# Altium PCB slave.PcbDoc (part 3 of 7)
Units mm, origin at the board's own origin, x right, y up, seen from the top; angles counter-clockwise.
Board outline 160 x 100 mm, 6 copper layers (Top, FUSED_VBAT-, Signals1, Signals2, SUPPLY, Bottom), stack 1.67 mm thick; 597 components, 381 nets, 1695 pads, 3028 vias.
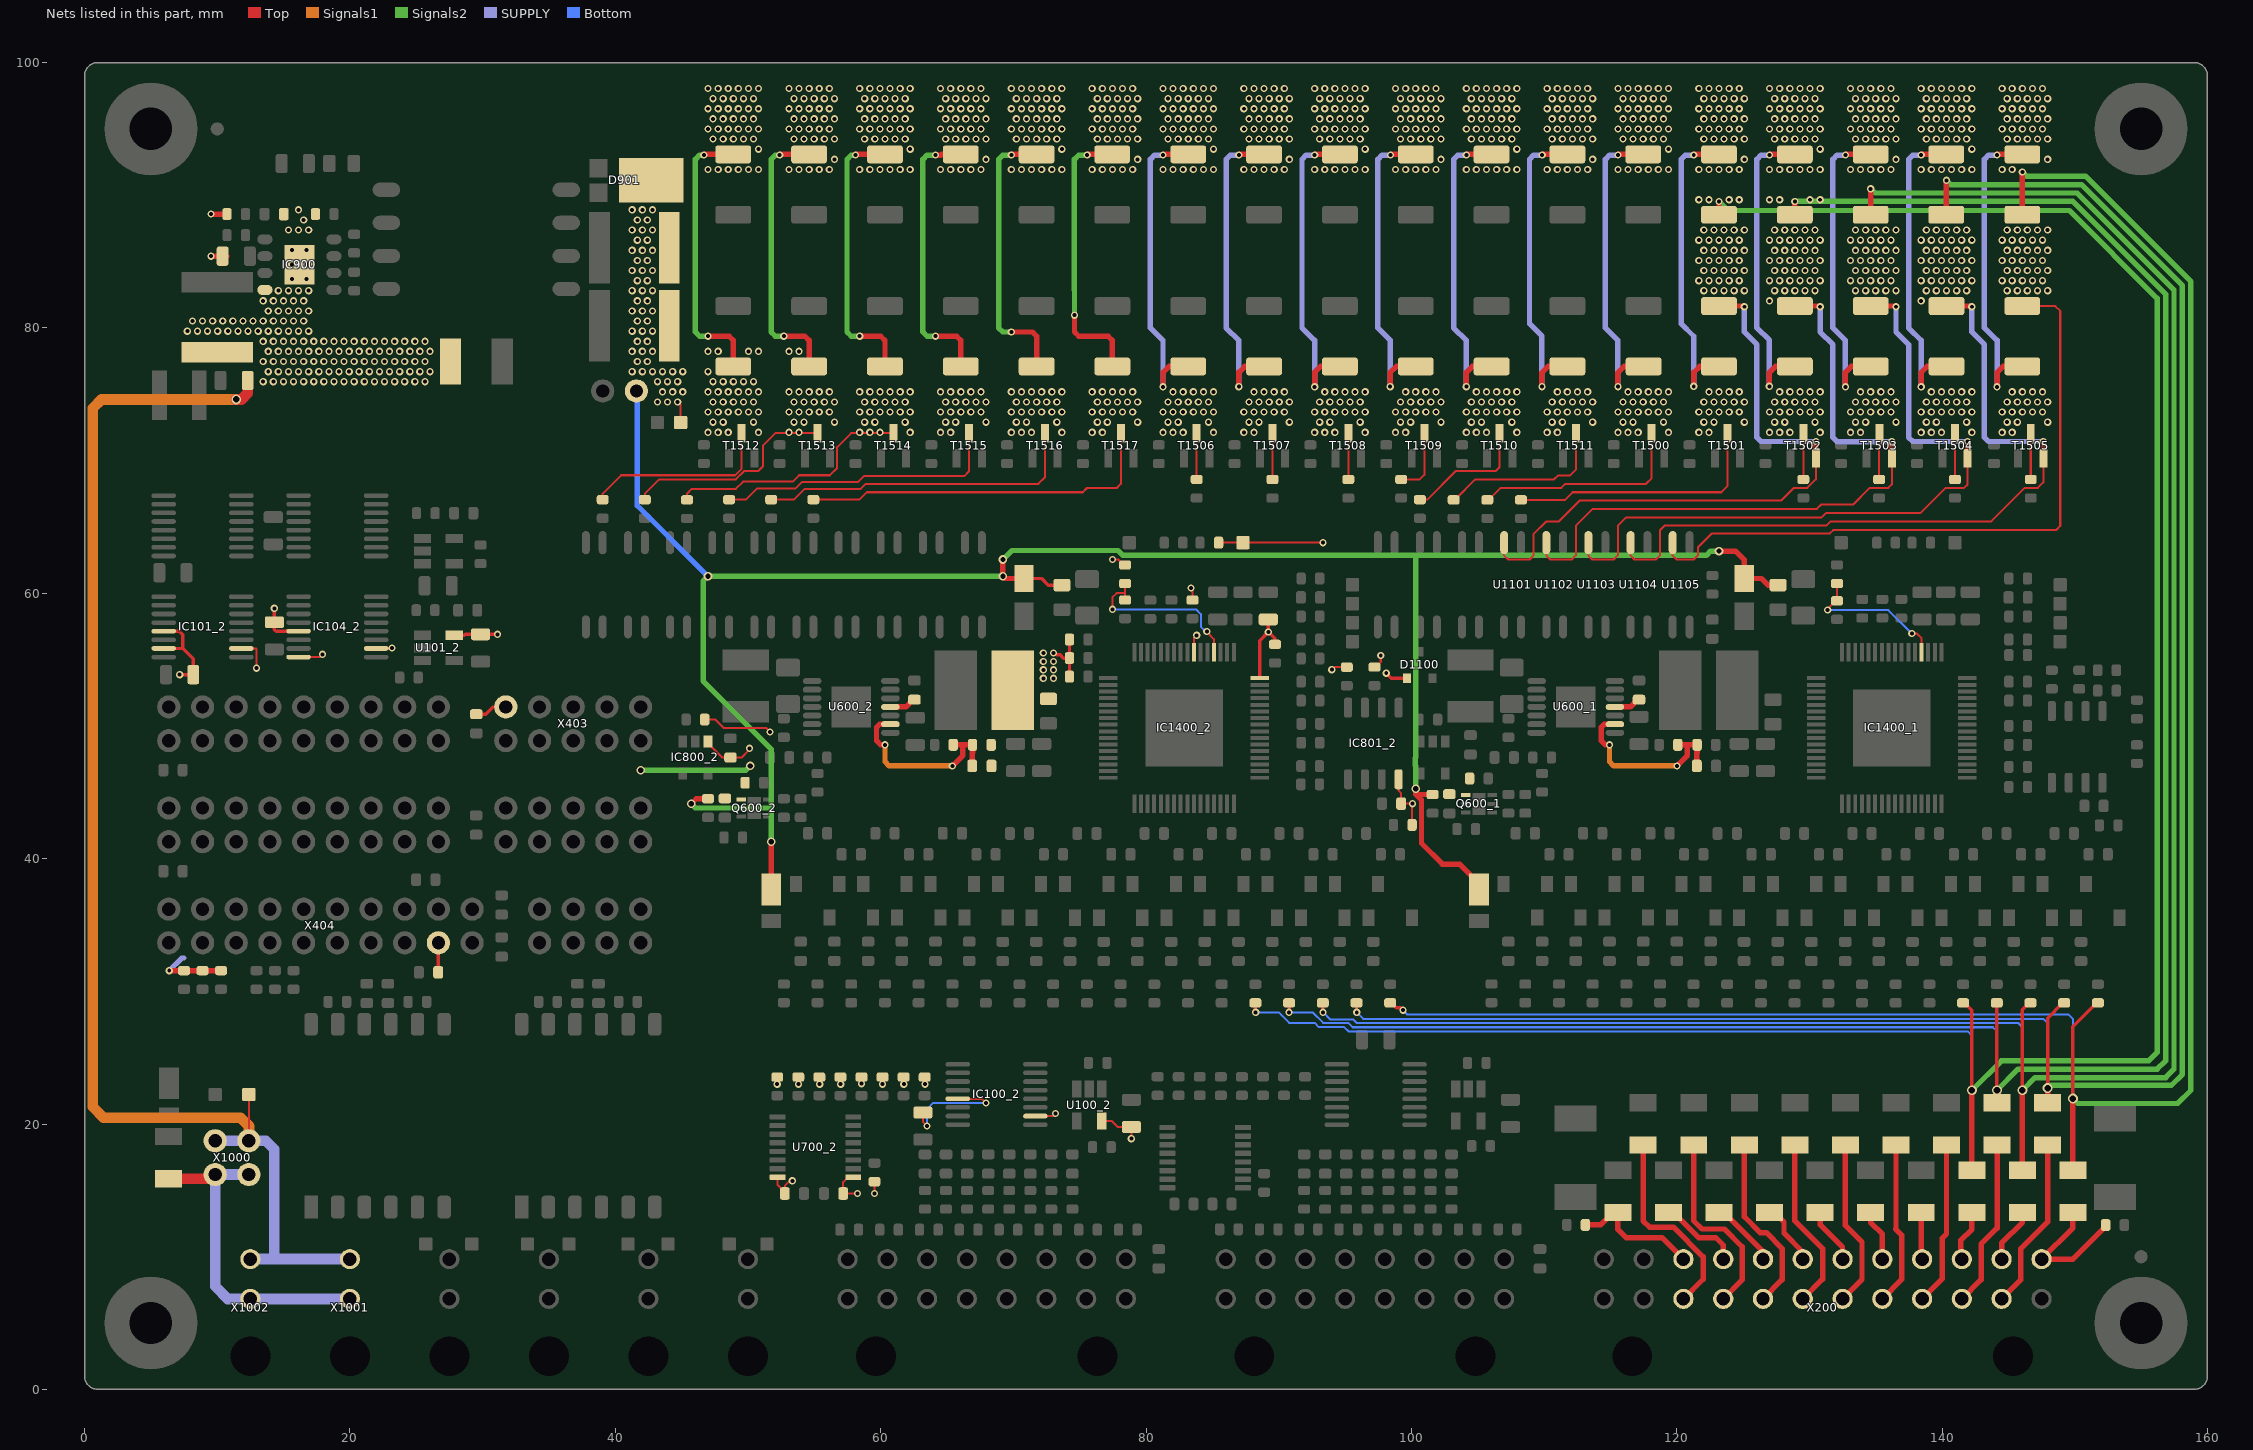
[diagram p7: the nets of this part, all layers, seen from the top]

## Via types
v1: diameter 0.55, hole 0.3, Top to Bottom, tented both sides, 2990 vias
v2: diameter 0.75, hole 0.5, Top to Bottom, tented both sides, 22 vias
v3: diameter 0.65, hole 0.4, Top to Bottom, tented both sides, 16 vias

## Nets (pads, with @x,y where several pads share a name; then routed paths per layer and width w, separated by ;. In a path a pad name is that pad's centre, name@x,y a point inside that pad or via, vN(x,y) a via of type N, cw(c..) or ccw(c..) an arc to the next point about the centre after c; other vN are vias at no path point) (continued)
+5.0V_VREG_1: C101_2.2 C102_2.2 C103_2.2 C104_2.2 C105_2.2 C403.2 C407.2 C604_2.2 C700_2.2 C701_2.2 C800_2.2 C801_2.2 C1401_2.2 D1100.1 IC100_2.2 IC100_2.13 IC101_2.2 IC101_2.13 IC101_2.15 IC104_2.2 IC104_2.13 IC104_2.16 IC800_2.1 IC801_2.8 IC1400_2.48 IC1400_2.55 L600_2.2 LD1400_2.2 R602_2.1 R604_2.1 R700_2.2 R701_2.2 R702_2.2 R703_2.2 R704_2.2 R705_2.2 R706_2.2 R707_2.2 R708_2.1 R800_2.2 R801_2.2 R1404_2.2 R1407_2.2 R1419_2.2 R1420_2.2 R1421_2.2 R1422_2.2 R1423_2.2 R1424_2.2 R1425_2.2 R1426_2.2 R1427_2.2 TP1403_2.1 U100_2.5 U101_2.5 U700_2.1 U700_2.16 X403.9 X404.4 | length 102.8
  Top w0.152: IC101_2.2@11.786,55.842 12.921,55.842 12.954,55.809 v1(12.954,54.356) ; IC104_2.16@16.125,55.193 17.728,55.193 v1(17.939,55.404) ; IC104_2.2@21.946,55.842 23.139,55.842 v1(23.177,55.88) ; R800_2.2@46.737,50.482 47.554,50.482 48.189,49.847 51.363,49.847 v1(51.663,49.548) ; IC800_2.1@46.988,48.825 46.988,48.7 48.063,47.625 C800_2.2@48.677,47.625 49.53,47.625 50.109,48.204 v1(50.109,48.316) ; v1(52.205,23.006) R707_2.2@52.205,23.535 R707_2.2@52.205,23.585 ; U700_2.16@52.236,15.981 52.236,15.401 C700_2.2@52.774,14.864 ; C700_2.2@52.774,14.764 C700_2.2@52.774,14.864 ; v1(53.34,15.716) 53.15,15.716 52.774,15.34 C700_2.2@52.774,14.864 ; R706_2.2@53.792,23.535 53.792,23.026 v1(53.813,23.006) ; R706_2.2@53.792,23.585 53.813,23.565 R706_2.2@53.813,23.535 ; R705_2.2@55.38,23.535 55.38,23.026 v1(55.4,23.006) ; R705_2.2@55.38,23.585 55.4,23.565 R705_2.2@55.4,23.535 ; R704_2.2@56.967,23.535 56.967,23.026 v1(56.988,23.006) ; R704_2.2@56.967,23.585 56.988,23.565 R704_2.2@56.988,23.535 ; U700_2.1@57.936,15.981 57.536,15.981 57.18,15.625 C701_2.2@57.18,14.764 v1(58.261,14.764) ; v1(58.555,23.044) R703_2.2@58.555,23.535 ; R703_2.2@58.555,23.585 R703_2.2@58.58,23.56 ; v1(59.531,14.764) R708_2.1@59.531,15.651 ; v1(60.142,23.006) R702_2.2@60.142,23.535 R702_2.2@60.142,23.585 ; R701_2.2@61.73,23.535 61.73,23.026 v1(61.75,23.006) ; R701_2.2@61.73,23.585 61.75,23.565 R701_2.2@61.75,23.535 ; C101_2.2@63.182,20.869 63.182,20.161 v1(63.5,19.844) ; R700_2.2@63.317,23.535 63.317,23.026 v1(63.338,23.006) ; R700_2.2@63.317,23.585 63.338,23.565 R700_2.2@63.338,23.535 ; IC100_2.13@65.814,21.9 67.635,21.9 v1(67.945,21.59) ; IC100_2.2@71.664,20.6 72.988,20.6 v1(73.184,20.796) 73.184,20.637 v1@73.146,20.6 ; U100_2.5@76.674,20.231 77.4,20.231 77.86,19.771 C103_2.2@78.899,19.771 v1(78.899,18.891) ; v1(77.47,62.547) 77.911,62.547 78.323,62.136 R1407_2.2@78.422,62.136 ; v1(83.384,60.397) 83.502,60.279 R1404_2.2@83.502,59.488 ; IC1400_2.55@83.618,55.598 83.618,56.63 v1(83.82,56.832) ; LD1400_2.2@85.523,63.817 TP1403_2.1@87.312,63.817 v1(93.345,63.817) ; v1(94.005,54.245) 94.194,54.434 R1419_2.2@95.135,54.434 ; R1420_2.2@97.223,54.437 97.323,54.437 97.693,54.808 v1(97.693,55.309) ; IC801_2.8@99.04,45.98 99.04,45.128 99.235,44.933 C801_2.2@99.235,44.147 v1(100.081,44.147) 100.057,44.124 R801_2.2@100.057,42.545
  Top w0.254: IC101_2.15@5.965,55.843 7.403,55.843 ; IC101_2.13@5.965,57.143 7.119,57.143 7.396,56.866 7.396,55.85 7.403,55.843 ; v1(7.166,53.868) C102_2.2@8.191,53.868 8.191,55.055 7.403,55.843 ; v1(14.306,58.864) C105_2.2@14.306,57.818 14.306,57.266 14.429,57.143 IC104_2.13@16.125,57.143 ; C407.2@26.65,31.432 C407.2@26.65,31.5 ; C407.2@26.67,31.52 C407.2@26.65,31.5 ; X404.4@26.67,33.655 26.65,33.635 C407.2@26.65,31.507 ; U101_2.5@27.87,56.83 28.622,56.83 28.697,56.905 C104_2.2@29.845,56.905 v1(31.115,56.905) ; C403.2@29.527,50.89 30.245,50.89 30.777,51.423 X403.9@31.75,51.435 ; 73.279,55.372 73.524,55.372 73.778,55.118 R1422_2.2@74.23,55.118 ; R1421_2.2@74.23,53.721 R1422_2.2@74.23,55.118 ; R1423_2.2@74.23,56.515 R1422_2.2@74.23,55.118 ; IC1400_2.48@88.568,53.597 88.568,56.433 v1(89.218,57.083) ; C1401_2.2@89.218,58.03 v1(89.218,57.083) ; R1424_2.2@89.725,56.152 89.725,56.604 89.697,56.604 v1(89.218,57.083) ; v1(98.108,53.975) 98.485,53.598 D1100.1@99.677,53.598 ; C407.2@26.65,31.5 26.583,31.432 26.613,31.466 C407.2@26.65,31.507 ; C407.2@26.65,31.5 C407.2@26.65,31.507
  Top w0.406: v1@6.35,31.561 v1(6.381,31.561) R1427_2.2@7.493,31.561 R1426_2.2@8.89,31.561 R1425_2.2@10.287,31.561
  Signals2 w0.406: v3(41.91,46.672) 49.847,46.672 v3(50.165,46.99)
  SUPPLY w0.406: v1(6.381,31.561) 7.332,32.512 7.493,32.512
  Bottom w0.152: v1(63.5,19.844) 63.5,21.114 63.976,21.59 v1(67.945,21.59)
  other v1: 72.263,53.594 73.025,53.594 72.263,54.229 73.025,54.229 72.263,54.864 73.025,54.864 72.263,55.499 73.025,55.499
BST_1: C602_1.2 U600_1.11 | length 2
  Top w0.406: U600_1.11@115.345,51.435 116.513,51.435 117.058,51.98 C602_1.2@117.157,51.98
BST_2: C602_2.2 U600_2.11 | length 2
  Top w0.406: U600_2.11@60.735,51.435 61.903,51.435 62.448,51.98 C602_2.2@62.547,51.98
CELL_0+: F318.1 X200.2 | length 13.3
  Top w0.406: X200.2@144.487,6.818 145.94,8.271 145.94,10.611 147.955,12.626 F318.1@147.955,18.413 ; F318.1@147.955,18.413 F318.1@147.955,18.652
CELL_0-: F319.1 SJ301.1 X200.13 | length 10.5
  Top w0.406: F319.1@149.86,13.333 149.86,12.178 X200.13@147.497,9.815 149.868,9.815 152.335,12.283 SJ301.1@152.335,12.383
CELL_1+: F317.1 X200.14 | length 4.2
  Top w0.406: X200.14@144.487,9.815 144.487,11.018 146.05,12.581 F317.1@146.05,13.333
CELL_2+: F316.1 X200.3 | length 12.9
  Top w0.406: X200.3@141.49,6.818 142.945,8.273 142.945,10.954 144.145,12.154 F316.1@144.145,18.413 ; F316.1@144.145,18.413 F316.1@144.145,18.652
CELL_3+: F315.1 X200.15 | length 3.9
  Top w0.406: X200.15@141.49,9.815 141.415,9.89 141.415,11.24 142.24,12.065 F315.1@142.24,13.333
CELL_4+: F314.1 X200.4 | length 12.6
  Top w0.406: X200.4@138.493,6.818 140.017,8.343 140.017,11.407 140.335,11.725 F314.1@140.335,18.413 ; F314.1@140.335,18.413 F314.1@140.335,18.652
CELL_5+: F313.1 X200.16 | length 3.5
  Top w0.406: F313.1@138.43,13.333 138.43,9.878 X200.16@138.493,9.815
CELL_6+: F312.1 X200.5 | length 12.6
  Top w0.406: X200.5@135.496,6.818 136.955,8.277 136.955,11.635 136.505,12.085 136.525,12.105 F312.1@136.525,18.413 ; F312.1@136.525,18.413 F312.1@136.525,18.652
CELL_7+: F311.1 X200.17 | length 3.9
  Top w0.406: F311.1@134.62,13.333 134.62,12.581 135.496,11.705 X200.17@135.496,9.815
CELL_8+: F310.1 X200.6 | length 13
  Top w0.406: X200.6@132.499,6.818 133.965,8.284 133.965,11.105 132.715,12.355 F310.1@132.715,18.413 F310.1@132.715,18.652
CELL_9+: F309.1 X200.18 | length 4.2
  Top w0.406: F309.1@130.81,13.333 130.81,12.415 132.499,10.726 X200.18@132.499,9.815
CELL_10+: F308.1 X200.7 | length 13.3
  Top w0.406: F308.1@128.905,18.652 F308.1@128.905,18.413 128.905,12.7 130.994,10.611 130.994,8.311 X200.7@129.501,6.818
CELL_11+: F307.1 X200.19 | length 4.8
  Top w0.406: F307.1@127,13.333 127.365,13.333 128.087,12.611 128.087,11.772 129.501,10.358 X200.19@129.501,9.815
CELL_12+: F306.1 X200.8 | length 13.9
  Top w0.406: F306.1@125.095,18.652 F306.1@125.095,18.413 125.095,13.01 126.288,11.817 126.754,11.817 127.953,10.619 127.953,8.267 X200.8@126.504,6.818
CELL_13+: F305.1 X200.20 | length 5.1
  Top w0.406: F305.1@123.19,13.333 123.555,13.333 126.504,10.384 X200.20@126.504,9.815
CELL_14+: F304.1 X200.9 | length 14.9
  Top w0.406: F304.1@121.285,18.652 F304.1@121.285,18.413 121.285,12.704 121.904,12.085 123.6,12.085 124.936,10.749 124.936,8.247 X200.9@123.507,6.818
CELL_15+: F303.1 X200.21 | length 6.2
  Top w0.406: F303.1@119.38,13.333 119.745,13.333 121.648,11.43 122.943,11.43 123.507,10.866 X200.21@123.507,9.815
CELL_16+: F302.1 X200.10 | length 15.4
  Top w0.406: F302.1@117.475,18.652 F302.1@117.475,18.413 117.475,12.7 117.951,12.224 119.754,12.224 121.99,9.987 121.99,8.298 X200.10@120.51,6.818
CELL_17+: F301.1 SJ300.2 X200.22 | length 10
  Top w0.406: SJ300.2@113.115,12.395 114.267,12.395 115.205,13.333 F301.1@115.57,13.333 115.57,12.047 116.187,11.43 118.895,11.43 X200.22@120.51,9.815
CELL_FEEDBACK.CELL0_FEEDBACK+: R1105.1 R1505.2 R1511.2 T1505.3 | length 27.2
  Top w0.152: R1105.1@146.685,68.58 T1505.3@146.685,72.07
  Top w0.406: v1(144.145,75.565) 144.145,76.647 144.598,77.1 R1505.2@146.05,77.1 ; v1(144.145,93.027) 144.198,93.08 R1511.2@146.05,93.08
  SUPPLY w0.406: v1(144.145,75.565) 144.145,79.057 143.192,80.01 143.192,92.71 143.51,93.027 v1(144.145,93.027)
  other v1: 144.526,72.136 145.288,72.136 144.907,72.898 145.669,72.898 147.955,72.898 144.526,73.66 145.288,73.66 146.05,73.66 146.812,73.66 147.574,73.66 144.907,74.422 145.669,74.422 146.431,74.422 147.193,74.422 147.955,74.422 145.288,75.184 146.05,75.184 146.812,75.184 147.574,75.184 144.526,91.948 145.288,91.948 147.955,92.71 144.907,94.234 145.669,94.234 146.431,94.234 147.193,94.234 147.955,94.234 144.526,94.996 145.288,94.996 146.05,94.996 146.812,94.996 147.574,94.996 144.907,95.758 145.669,95.758 146.431,95.758 147.193,95.758 147.955,95.758 144.526,96.52 145.288,96.52 146.05,96.52 146.812,96.52 147.574,96.52 144.907,97.282 145.669,97.282 146.431,97.282 147.193,97.282 147.955,97.282 144.526,98.044 145.288,98.044 146.05,98.044 146.812,98.044 147.574,98.044
CELL_FEEDBACK.CELL1_FEEDBACK+: R1104.1 R1504.2 R1510.2 T1504.3 | length 27.2
  Top w0.152: R1104.1@140.97,68.58 T1504.3@140.97,72.07
  Top w0.406: v1(138.43,75.565) 138.43,76.647 138.883,77.1 R1504.2@140.335,77.1 ; v1(138.43,93.027) 138.483,93.08 R1510.2@140.315,93.08
  SUPPLY w0.406: v1(138.43,75.565) 138.43,79.057 137.477,80.01 137.477,92.71 137.795,93.027 v1(138.43,93.027)
  other v1: 138.43,72.136 139.192,72.136 139.954,72.136 142.24,72.136 138.811,72.898 139.573,72.898 141.859,72.898 138.43,73.66 139.192,73.66 139.954,73.66 140.716,73.66 141.478,73.66 142.24,73.66 138.811,74.422 139.573,74.422 140.335,74.422 141.097,74.422 141.859,74.422 139.192,75.184 139.954,75.184 140.716,75.184 141.478,75.184 142.24,75.184 138.43,91.948 139.192,91.948 139.954,91.948 140.716,91.948 141.478,91.948 142.24,91.948 142.24,93.472 138.811,94.234 139.573,94.234 140.335,94.234 141.097,94.234 141.859,94.234 138.43,94.996 139.192,94.996 139.954,94.996 140.716,94.996 141.478,94.996 142.24,94.996 138.811,95.758 139.573,95.758 140.335,95.758 141.097,95.758 141.859,95.758 138.43,96.52 139.192,96.52 139.954,96.52 140.716,96.52 141.478,96.52 142.24,96.52 138.811,97.282 139.573,97.282 140.335,97.282 141.097,97.282 141.859,97.282 138.43,98.044 139.192,98.044 139.954,98.044 140.716,98.044 141.478,98.044 142.24,98.044
CELL_FEEDBACK.CELL2_FEEDBACK+: R1103.1 R1503.2 R1509.2 T1503.3 | length 27.2
  Top w0.152: R1103.1@135.255,68.58 135.255,71.256 135.267,71.268 T1503.3@135.267,72.07
  Top w0.406: v1(132.715,75.565) 132.715,76.647 133.168,77.1 R1503.2@134.62,77.1 ; v1(132.715,93.027) 132.768,93.08 R1509.2@134.62,93.08
  SUPPLY w0.406: v1(132.715,75.565) 132.715,79.057 131.762,80.01 131.762,92.71 132.08,93.027 v1(132.715,93.027)
  other v1: 133.096,72.136 133.858,72.136 133.477,72.898 134.239,72.898 136.525,72.898 133.096,73.66 133.858,73.66 134.62,73.66 135.382,73.66 136.144,73.66 133.477,74.422 134.239,74.422 135.001,74.422 135.763,74.422 136.525,74.422 133.858,75.184 134.62,75.184 135.382,75.184 136.144,75.184 133.096,91.948 133.858,91.948 134.62,91.948 135.382,91.948 136.144,91.948 136.525,92.71 133.477,94.234 134.239,94.234 135.001,94.234 135.763,94.234 136.525,94.234 133.096,94.996 133.858,94.996 134.62,94.996 135.382,94.996 136.144,94.996 133.477,95.758 134.239,95.758 135.001,95.758 135.763,95.758 136.525,95.758 133.096,96.52 133.858,96.52 134.62,96.52 135.382,96.52 136.144,96.52 133.477,97.282 134.239,97.282 135.001,97.282 135.763,97.282 136.525,97.282 133.096,98.044 133.858,98.044 134.62,98.044 135.382,98.044 136.144,98.044
CELL_FEEDBACK.CELL3_FEEDBACK+: R1102.1 R1502.2 R1508.2 T1502.3 | length 27.2
  Top w0.152: R1102.1@129.54,68.58 T1502.3@129.54,72.07
  Top w0.406: v1(126.982,75.595) 126.982,76.628 127.453,77.1 R1502.2@128.905,77.1 ; v1(127,93.027) 127.053,93.08 R1508.2@128.905,93.08
  SUPPLY w0.406: v1@127,75.614 v1(126.982,75.595) 126.982,79.076 126.047,80.01 126.047,92.71 126.365,93.027 v1(127,93.027)
  other v1: 127,72.136 127.762,72.136 128.524,72.136 130.81,72.136 127.381,72.898 128.143,72.898 130.429,72.898 127,73.66 127.762,73.66 128.524,73.66 129.286,73.66 130.048,73.66 130.81,73.66 127.381,74.422 128.143,74.422 128.905,74.422 129.667,74.422 130.429,74.422 127.762,75.184 128.524,75.184 129.286,75.184 130.048,75.184 130.81,75.184 127,91.948 127.762,91.948 128.524,91.948 129.286,91.948 130.048,91.948 130.81,91.948 130.81,93.472 127.381,94.234 128.143,94.234 128.905,94.234 129.667,94.234 130.429,94.234 127,94.996 127.762,94.996 128.524,94.996 129.286,94.996 130.048,94.996 130.81,94.996 127.381,95.758 128.143,95.758 128.905,95.758 129.667,95.758 130.429,95.758 127,96.52 127.762,96.52 128.524,96.52 129.286,96.52 130.048,96.52 130.81,96.52 127.381,97.282 128.143,97.282 128.905,97.282 129.667,97.282 130.429,97.282 127,98.044 127.762,98.044 128.524,98.044 129.286,98.044 130.048,98.044 130.81,98.044
CELL_FEEDBACK.CELL4_FEEDBACK+: R1101.1 R1501.2 R1507.2 T1501.3 | length 43.6
  Top w0.152: R1101.1@108.267,67.045 111.587,67.045 112.157,67.615 123.36,67.615 123.825,68.08 T1501.3@123.825,72.07
  Top w0.406: v1(121.285,75.595) 121.285,76.647 121.738,77.1 R1501.2@123.19,77.1 ; v1(121.285,93.027) 121.338,93.08 R1507.2@123.19,93.08
  SUPPLY w0.406: v1(121.285,75.595) 121.285,79.375 120.332,80.328 120.332,92.71 120.65,93.027 v1(121.285,93.027)
  other v1: 121.666,72.136 122.428,72.136 122.047,72.898 122.809,72.898 125.095,72.898 121.666,73.66 122.428,73.66 123.19,73.66 123.952,73.66 124.714,73.66 122.047,74.422 122.809,74.422 123.571,74.422 124.333,74.422 125.095,74.422 122.428,75.184 123.19,75.184 123.952,75.184 124.714,75.184 121.666,91.948 122.428,91.948 123.19,91.948 123.952,91.948 124.714,91.948 125.095,92.71 122.047,94.234 122.809,94.234 123.571,94.234 124.333,94.234 125.095,94.234 121.666,94.996 122.428,94.996 123.19,94.996 123.952,94.996 124.714,94.996 122.047,95.758 122.809,95.758 123.571,95.758 124.333,95.758 125.095,95.758 121.666,96.52 122.428,96.52 123.19,96.52 123.952,96.52 124.714,96.52 122.047,97.282 122.809,97.282 123.571,97.282 124.333,97.282 125.095,97.282 121.666,98.044 122.428,98.044 123.19,98.044 123.952,98.044 124.714,98.044
CELL_FEEDBACK.CELL5_FEEDBACK+: R1100.1 R1500.2 R1506.2 T1500.3 | length 40.2
  Top w0.152: R1100.1@105.727,67.045 105.827,67.045 106.727,67.945 111.308,67.945 111.613,68.25 117.688,68.25 118.11,68.673 T1500.3@118.11,72.07
  Top w0.406: v1(115.57,75.575) 115.57,76.627 116.043,77.1 R1500.2@117.505,77.1 ; v1(115.57,93.027) 115.623,93.08 R1506.2@117.475,93.08
  SUPPLY w0.406: v1(115.57,75.575) 115.57,79.057 114.617,80.01 114.617,92.71 114.935,93.027 v1(115.57,93.027)
  other v1: 115.57,72.136 116.332,72.136 117.094,72.136 119.38,72.136 115.951,72.898 116.713,72.898 118.999,72.898 115.57,73.66 116.332,73.66 117.094,73.66 117.856,73.66 118.618,73.66 119.38,73.66 115.951,74.422 116.713,74.422 117.475,74.422 118.237,74.422 118.999,74.422 116.332,75.184 117.094,75.184 117.856,75.184 118.618,75.184 119.38,75.184 115.57,91.948 116.332,91.948 117.094,91.948 117.856,91.948 118.618,91.948 119.38,91.948 119.38,93.472 115.951,94.234 116.713,94.234 117.475,94.234 118.237,94.234 118.999,94.234 115.57,94.996 116.332,94.996 117.094,94.996 117.856,94.996 118.618,94.996 119.38,94.996 115.951,95.758 116.713,95.758 117.475,95.758 118.237,95.758 118.999,95.758 115.57,96.52 116.332,96.52 117.094,96.52 117.856,96.52 118.618,96.52 119.38,96.52 115.951,97.282 116.713,97.282 117.475,97.282 118.237,97.282 118.999,97.282 115.57,98.044 116.332,98.044 117.094,98.044 117.856,98.044 118.618,98.044 119.38,98.044
CELL_FEEDBACK.CELL6_FEEDBACK+: R1111.1 R1523.2 R1529.2 T1511.3 | length 36.6
  Top w0.152: R1111.1@103.188,67.045 103.287,67.045 104.824,68.581 110.754,68.581 111.057,68.885 111.965,68.885 112.395,69.315 T1511.3@112.395,72.07
  Top w0.406: v1(109.843,75.575) 109.843,76.634 110.308,77.1 R1523.2@111.76,77.1 ; v1(109.855,93.027) 109.908,93.08 R1529.2@111.76,93.08
  SUPPLY w0.406: v1@109.855,75.588 v1(109.843,75.575) 109.843,79.387 108.902,80.328 108.902,92.71 109.22,93.027 v1(109.855,93.027)
  other v1: 110.236,72.136 110.998,72.136 110.617,72.898 111.379,72.898 113.665,72.898 110.236,73.66 110.998,73.66 111.76,73.66 112.522,73.66 113.284,73.66 110.617,74.422 111.379,74.422 112.141,74.422 112.903,74.422 113.665,74.422 110.998,75.184 111.76,75.184 112.522,75.184 113.284,75.184 110.236,91.948 110.998,91.948 111.76,91.948 112.522,91.948 113.284,91.948 113.665,92.71 110.617,94.234 111.379,94.234 112.141,94.234 112.903,94.234 113.665,94.234 110.236,94.996 110.998,94.996 111.76,94.996 112.522,94.996 113.284,94.996 110.617,95.758 111.379,95.758 112.141,95.758 112.903,95.758 113.665,95.758 110.236,96.52 110.998,96.52 111.76,96.52 112.522,96.52 113.284,96.52 110.617,97.282 111.379,97.282 112.141,97.282 112.903,97.282 113.665,97.282 110.236,98.044 110.998,98.044 111.76,98.044 112.522,98.044 113.284,98.044
CELL_FEEDBACK.CELL7_FEEDBACK+: R1110.1 R1522.2 R1528.2 T1510.3 | length 33.3
  Top w0.152: R1110.1@100.642,67.058 101.194,67.058 103.356,69.22 106.362,69.22 106.66,69.517 T1510.3@106.66,72.07
  Top w0.406: v1(104.14,75.575) 104.14,76.647 104.593,77.1 R1522.2@106.045,77.1 ; v1(104.14,93.027) 104.193,93.08 R1528.2@106.045,93.08
  SUPPLY w0.406: v1(104.14,75.575) 104.14,79.057 103.188,80.01 103.188,92.71 103.505,93.027 v1(104.14,93.027)
  other v1: 104.14,72.136 104.902,72.136 105.664,72.136 107.95,72.136 104.521,72.898 105.283,72.898 107.569,72.898 104.14,73.66 104.902,73.66 105.664,73.66 106.426,73.66 107.188,73.66 107.95,73.66 104.521,74.422 105.283,74.422 106.045,74.422 106.807,74.422 107.569,74.422 104.902,75.184 105.664,75.184 106.426,75.184 107.188,75.184 107.95,75.184 104.14,91.948 104.902,91.948 105.664,91.948 106.426,91.948 107.188,91.948 107.95,91.948 107.95,93.472 104.521,94.234 105.283,94.234 106.045,94.234 106.807,94.234 107.569,94.234 104.14,94.996 104.902,94.996 105.664,94.996 106.426,94.996 107.188,94.996 107.95,94.996 104.521,95.758 105.283,95.758 106.045,95.758 106.807,95.758 107.569,95.758 104.14,96.52 104.902,96.52 105.664,96.52 106.426,96.52 107.188,96.52 107.95,96.52 104.521,97.282 105.283,97.282 106.045,97.282 106.807,97.282 107.569,97.282 104.14,98.044 104.902,98.044 105.664,98.044 106.426,98.044 107.188,98.044 107.95,98.044
CELL_FEEDBACK.CELL8_FEEDBACK+: R1109.1 R1521.2 R1527.2 T1509.3 | length 28.7
  Top w0.152: R1109.1@99.235,68.58 100.631,68.58 100.98,68.929 T1509.3@100.98,72.07
  Top w0.406: v1(98.405,75.575) 98.405,76.627 98.878,77.1 R1521.2@100.33,77.1 ; v1(98.425,93.027) 98.478,93.08 R1527.2@100.33,93.08
  SUPPLY w0.406: v1(98.405,75.575) 98.405,79.078 97.472,80.01 97.472,92.71 97.79,93.027 v1(98.425,93.027)
  other v1: 98.806,72.136 99.568,72.136 99.187,72.898 99.949,72.898 102.235,72.898 98.806,73.66 99.568,73.66 100.33,73.66 101.092,73.66 101.854,73.66 99.187,74.422 99.949,74.422 100.711,74.422 101.473,74.422 102.235,74.422 99.568,75.184 100.33,75.184 101.092,75.184 101.854,75.184 98.806,91.948 99.568,91.948 100.33,91.948 101.092,91.948 101.854,91.948 102.235,92.71 99.187,94.234 99.949,94.234 100.711,94.234 101.473,94.234 102.235,94.234 98.806,94.996 99.568,94.996 100.33,94.996 101.092,94.996 101.854,94.996 99.187,95.758 99.949,95.758 100.711,95.758 101.473,95.758 102.235,95.758 98.806,96.52 99.568,96.52 100.33,96.52 101.092,96.52 101.854,96.52 99.187,97.282 99.949,97.282 100.711,97.282 101.473,97.282 102.235,97.282 98.806,98.044 99.568,98.044 100.33,98.044 101.092,98.044 101.854,98.044
CELL_FEEDBACK.CELL9_FEEDBACK+: R1108.1 R1520.2 R1526.2 T1508.3 | length 27.2
  Top w0.152: R1108.1@95.25,68.58 T1508.3@95.25,72.07
  Top w0.406: v1(92.71,75.565) 92.71,76.647 93.163,77.1 R1520.2@94.615,77.1 ; v1(92.71,93.027) 92.763,93.08 R1526.2@94.615,93.08
  SUPPLY w0.406: v1(92.71,75.565) 92.71,79.057 91.757,80.01 91.757,92.71 92.075,93.027 v1(92.71,93.027)
  other v1: 92.71,72.136 93.472,72.136 94.234,72.136 96.52,72.136 93.091,72.898 93.853,72.898 96.139,72.898 92.71,73.66 93.472,73.66 94.234,73.66 94.996,73.66 95.758,73.66 96.52,73.66 93.091,74.422 93.853,74.422 94.615,74.422 95.377,74.422 96.139,74.422 93.472,75.184 94.234,75.184 94.996,75.184 95.758,75.184 96.52,75.184 92.71,91.948 93.472,91.948 94.234,91.948 94.996,91.948 95.758,91.948 96.52,91.948 96.52,93.472 93.091,94.234 93.853,94.234 94.615,94.234 95.377,94.234 96.139,94.234 92.71,94.996 93.472,94.996 94.234,94.996 94.996,94.996 95.758,94.996 96.52,94.996 93.091,95.758 93.853,95.758 94.615,95.758 95.377,95.758 96.139,95.758 92.71,96.52 93.472,96.52 94.234,96.52 94.996,96.52 95.758,96.52 96.52,96.52 93.091,97.282 93.853,97.282 94.615,97.282 95.377,97.282 96.139,97.282 92.71,98.044 93.472,98.044 94.234,98.044 94.996,98.044 95.758,98.044 96.52,98.044
CELL_FEEDBACK.CELL10_FEEDBACK+: R1107.1 R1519.2 R1525.2 T1507.3 | length 27.2
  Top w0.152: R1107.1@89.535,68.58 T1507.3@89.535,72.07
  Top w0.406: v1(86.995,75.575) 86.995,76.647 87.448,77.1 R1519.2@88.9,77.1 ; v1(86.995,93.027) 87.048,93.08 R1525.2@88.9,93.08
  SUPPLY w0.406: v1@86.995,75.565 v1(86.995,75.575) 86.995,79.057 86.042,80.01 86.042,92.71 86.36,93.027 v1(86.995,93.027)
  other v1: 87.376,72.136 88.138,72.136 87.757,72.898 88.519,72.898 90.805,72.898 87.376,73.66 88.138,73.66 88.9,73.66 89.662,73.66 90.424,73.66 87.757,74.422 88.519,74.422 89.281,74.422 90.043,74.422 90.805,74.422 88.138,75.184 88.9,75.184 89.662,75.184 90.424,75.184 87.376,91.948 88.138,91.948 88.9,91.948 89.662,91.948 90.424,91.948 90.805,92.71 87.757,94.234 88.519,94.234 89.281,94.234 90.043,94.234 90.805,94.234 87.376,94.996 88.138,94.996 88.9,94.996 89.662,94.996 90.424,94.996 87.757,95.758 88.519,95.758 89.281,95.758 90.043,95.758 90.805,95.758 87.376,96.52 88.138,96.52 88.9,96.52 89.662,96.52 90.424,96.52 87.757,97.282 88.519,97.282 89.281,97.282 90.043,97.282 90.805,97.282 87.376,98.044 88.138,98.044 88.9,98.044 89.662,98.044 90.424,98.044
CELL_FEEDBACK.CELL11_FEEDBACK+: R1106.1 R1518.2 R1524.2 T1506.3 | length 27.2
  Top w0.152: R1106.1@83.82,68.58 T1506.3@83.82,72.07
  Top w0.406: v1(81.28,75.565) 81.28,76.647 81.733,77.1 R1518.2@83.185,77.1 ; v1(81.28,93.027) 81.333,93.08 R1524.2@83.185,93.08
  SUPPLY w0.406: v1(81.28,75.565) 81.28,79.057 80.328,80.01 80.328,92.71 80.645,93.027 v1(81.28,93.027)
  other v1: 81.28,72.136 82.042,72.136 82.804,72.136 85.09,72.136 81.661,72.898 82.423,72.898 84.709,72.898 81.28,73.66 82.042,73.66 82.804,73.66 83.566,73.66 84.328,73.66 85.09,73.66 81.661,74.422 82.423,74.422 83.185,74.422 83.947,74.422 84.709,74.422 82.042,75.184 82.804,75.184 83.566,75.184 84.328,75.184 85.09,75.184 81.28,91.948 82.042,91.948 82.804,91.948 83.566,91.948 84.328,91.948 85.09,91.948 85.09,93.472 81.661,94.234 82.423,94.234 83.185,94.234 83.947,94.234 84.709,94.234 81.28,94.996 82.042,94.996 82.804,94.996 83.566,94.996 84.328,94.996 85.09,94.996 81.661,95.758 82.423,95.758 83.185,95.758 83.947,95.758 84.709,95.758 81.28,96.52 82.042,96.52 82.804,96.52 83.566,96.52 84.328,96.52 85.09,96.52 81.661,97.282 82.423,97.282 83.185,97.282 83.947,97.282 84.709,97.282 81.28,98.044 82.042,98.044 82.804,98.044 83.566,98.044 84.328,98.044 85.09,98.044
CELL_FEEDBACK.CELL12_FEEDBACK+: R1117.1 R1541.2 R1547.2 T1517.3 | length 48.6
  Top w0.152: R1117.1@54.915,67.058 58.402,67.058 58.959,67.615 75.235,67.615 75.555,67.935 77.795,67.935 78.105,68.245 T1517.3@78.105,72.07
  Top w0.406: v1(74.612,80.962) 74.612,79.692 74.93,79.375 77.153,79.375 77.465,79.062 R1541.2@77.465,77.1 ; v1(75.565,93.027) 75.618,93.08 R1547.2@77.45,93.08
  Signals2 w0.406: 74.602,82.867 74.602,92.7 74.93,93.027 v1(75.565,93.027) ; v1(74.612,80.962) 74.612,82.867
  other v1: 75.946,72.136 76.708,72.136 76.327,72.898 77.089,72.898 79.375,72.898 75.946,73.66 76.708,73.66 77.47,73.66 78.232,73.66 78.994,73.66 76.327,74.422 77.089,74.422 77.851,74.422 78.613,74.422 79.375,74.422 75.946,75.184 76.708,75.184 77.47,75.184 78.232,75.184 78.994,75.184 75.946,91.948 76.708,91.948 77.47,91.948 78.232,91.948 78.994,91.948 79.375,92.71 76.327,94.234 77.089,94.234 77.851,94.234 78.613,94.234 79.375,94.234 75.946,94.996 76.708,94.996 77.47,94.996 78.232,94.996 78.994,94.996 76.327,95.758 77.089,95.758 77.851,95.758 78.613,95.758 79.375,95.758 75.946,96.52 76.708,96.52 77.47,96.52 78.232,96.52 78.994,96.52 76.327,97.282 77.089,97.282 77.851,97.282 78.613,97.282 79.375,97.282 75.946,98.044 76.708,98.044 77.47,98.044 78.232,98.044 78.994,98.044
CELL_FEEDBACK.CELL13_FEEDBACK+: R1116.1 R1540.2 R1546.2 T1516.3 | length 45.8
  Top w0.152: R1116.1@51.752,67.058 53.455,67.058 54.266,67.869 58.495,67.869 58.87,68.245 71.893,68.245 72.39,68.741 T1516.3@72.39,72.07
  Top w0.406: v1(69.85,79.692) 71.438,79.692 71.755,79.375 R1540.2@71.755,77.1 ; v1(69.85,93.027) 69.903,93.08 R1546.2@71.755,93.08
  Signals2 w0.406: v1(69.85,79.692) 69.215,79.692 68.897,80.01 68.897,92.71 69.215,93.027 v1(69.85,93.027)
  other v1: 69.85,72.136 70.612,72.136 71.374,72.136 73.66,72.136 70.231,72.898 70.993,72.898 73.279,72.898 69.85,73.66 70.612,73.66 71.374,73.66 72.136,73.66 72.898,73.66 73.66,73.66 70.231,74.422 70.993,74.422 71.755,74.422 72.517,74.422 73.279,74.422 69.85,75.184 70.612,75.184 71.374,75.184 72.136,75.184 72.898,75.184 73.66,75.184 69.85,91.948 70.612,91.948 71.374,91.948 72.136,91.948 72.898,91.948 73.66,91.948 73.66,93.472 70.231,94.234 70.993,94.234 71.755,94.234 72.517,94.234 73.279,94.234 69.85,94.996 70.612,94.996 71.374,94.996 72.136,94.996 72.898,94.996 73.66,94.996 70.231,95.758 70.993,95.758 71.755,95.758 72.517,95.758 73.279,95.758 69.85,96.52 70.612,96.52 71.374,96.52 72.136,96.52 72.898,96.52 73.66,96.52 70.231,97.282 70.993,97.282 71.755,97.282 72.517,97.282 73.279,97.282 69.85,98.044 70.612,98.044 71.374,98.044 72.136,98.044 72.898,98.044 73.66,98.044
CELL_FEEDBACK.CELL14_FEEDBACK+: R1115.1 R1539.2 R1545.2 T1515.3 | length 43
  Top w0.152: R1115.1@48.578,67.058 49.847,67.058 50.701,67.911 53.59,67.911 54.056,68.377 58.284,68.377 58.741,68.834 66.294,68.834 66.675,69.215 T1515.3@66.675,72.07
  Top w0.406: v1(64.135,79.375) 65.722,79.375 66.04,79.057 R1539.2@66.04,77.1 ; v1(64.135,93.027) 64.536,93.027 64.588,93.08 R1545.2@66.04,93.08
  Signals2 w0.406: v1(64.135,79.375) 63.5,79.375 63.182,79.692 63.182,92.71 63.5,93.027 v1(64.135,93.027)
  other v1: 64.516,72.136 65.278,72.136 64.897,72.898 65.659,72.898 67.945,72.898 64.516,73.66 65.278,73.66 66.04,73.66 66.802,73.66 67.564,73.66 64.897,74.422 65.659,74.422 66.421,74.422 67.183,74.422 67.945,74.422 64.516,75.184 65.278,75.184 66.04,75.184 66.802,75.184 67.564,75.184 64.516,91.948 65.278,91.948 66.04,91.948 66.802,91.948 67.564,91.948 67.945,92.71 64.897,94.234 65.659,94.234 66.421,94.234 67.183,94.234 67.945,94.234 64.516,94.996 65.278,94.996 66.04,94.996 66.802,94.996 67.564,94.996 64.897,95.758 65.659,95.758 66.421,95.758 67.183,95.758 67.945,95.758 64.516,96.52 65.278,96.52 66.04,96.52 66.802,96.52 67.564,96.52 64.897,97.282 65.659,97.282 66.421,97.282 67.183,97.282 67.945,97.282 64.516,98.044 65.278,98.044 66.04,98.044 66.802,98.044 67.564,98.044
CELL_FEEDBACK.CELL15_FEEDBACK+: R1114.1 R1538.2 R1544.2 T1514.3 | length 39.9
  Top w0.152: R1114.1@45.402,67.045 45.402,67.497 45.775,67.869 49.086,67.869 49.636,68.419 53.38,68.419 53.858,68.897 56.174,68.897 56.723,69.446 56.723,71.023 57.77,72.07 T1514.3@60.96,72.07
  Top w0.406: v1(58.102,93.027) 58.155,93.08 R1544.2@60.325,93.08 ; v1(58.42,79.375) 60.008,79.375 60.325,79.057 R1538.2@60.325,77.1
  Signals2 w0.406: v1(58.102,93.027) 57.785,93.027 57.468,92.71 57.468,79.692 57.785,79.375 v1(58.42,79.375)
  other v1: 58.42,72.136 59.182,72.136 59.944,72.136 62.23,72.136 58.801,72.898 59.563,72.898 61.849,72.898 58.42,73.66 59.182,73.66 59.944,73.66 60.706,73.66 61.468,73.66 62.23,73.66 58.801,74.422 59.563,74.422 60.325,74.422 61.087,74.422 61.849,74.422 58.42,75.184 59.182,75.184 59.944,75.184 60.706,75.184 61.468,75.184 62.23,75.184 58.42,91.948 59.182,91.948 59.944,91.948 60.706,91.948 61.468,91.948 62.23,91.948 62.23,93.472 58.801,94.234 59.563,94.234 60.325,94.234 61.087,94.234 61.849,94.234 58.42,94.996 59.182,94.996 59.944,94.996 60.706,94.996 61.468,94.996 62.23,94.996 58.801,95.758 59.563,95.758 60.325,95.758 61.087,95.758 61.849,95.758 58.42,96.52 59.182,96.52 59.944,96.52 60.706,96.52 61.468,96.52 62.23,96.52 58.801,97.282 59.563,97.282 60.325,97.282 61.087,97.282 61.849,97.282 58.42,98.044 59.182,98.044 59.944,98.044 60.706,98.044 61.468,98.044 62.23,98.044
CELL_FEEDBACK.CELL16_FEEDBACK+: R1113.1 R1537.2 R1543.2 T1513.3 | length 37.3
  Top w0.152: R1113.1@42.227,67.058 42.227,67.509 43.298,68.58 49.079,68.58 49.714,69.215 50.776,69.215 51.117,69.556 51.117,71.12 52.067,72.07 T1513.3@55.245,72.07
  Top w0.406: v1(52.387,93.027) 52.44,93.08 R1543.2@54.61,93.08 ; v1(52.705,79.375) 54.292,79.375 54.61,79.057 54.61,77.877 R1537.2@54.61,77.1
  Signals2 w0.406: 51.752,81.269 51.752,79.692 52.07,79.375 v1(52.705,79.375) ; 51.752,81.315 51.752,92.71 52.07,93.027 v1(52.387,93.027)
  other v1: 53.086,72.136 53.848,72.136 53.467,72.898 54.229,72.898 56.515,72.898 53.086,73.66 53.848,73.66 54.61,73.66 55.372,73.66 56.134,73.66 53.467,74.422 54.229,74.422 54.991,74.422 55.753,74.422 56.515,74.422 53.086,75.184 53.848,75.184 54.61,75.184 55.372,75.184 56.134,75.184 53.086,78.232 53.848,78.232 53.086,91.948 53.848,91.948 54.61,91.948 55.372,91.948 56.134,91.948 56.515,92.71 53.467,94.234 54.229,94.234 54.991,94.234 55.753,94.234 56.515,94.234 53.086,94.996 53.848,94.996 54.61,94.996 55.372,94.996 56.134,94.996 53.467,95.758 54.229,95.758 54.991,95.758 55.753,95.758 56.515,95.758 53.086,96.52 53.848,96.52 54.61,96.52 55.372,96.52 56.134,96.52 53.467,97.282 54.229,97.282 54.991,97.282 55.753,97.282 56.515,97.282 53.086,98.044 53.848,98.044 54.61,98.044 55.372,98.044 56.134,98.044
CELL_FEEDBACK.CELL17_FEEDBACK+: R1112.1 R1536.2 R1542.2 T1512.3 | length 35.5
  Top w0.152: R1112.1@39.052,67.058 39.052,67.509 40.441,68.897 49.036,68.897 49.53,69.391 T1512.3@49.53,72.07
  Top w0.406: v1(46.672,93.027) 46.725,93.08 R1542.2@48.895,93.08 ; v1(46.99,79.375) 48.578,79.375 48.895,79.057 R1536.2@48.895,77.1
  Signals2 w0.406: v1(46.672,93.027) 46.355,93.027 46.038,92.71 46.038,79.692 46.355,79.375 v1(46.99,79.375)
  other v1: 46.99,72.136 47.752,72.136 48.514,72.136 50.8,72.136 47.371,72.898 48.133,72.898 50.419,72.898 46.99,73.66 47.752,73.66 48.514,73.66 49.276,73.66 50.038,73.66 50.8,73.66 47.371,74.422 48.133,74.422 48.895,74.422 49.657,74.422 50.419,74.422 46.99,75.184 47.752,75.184 48.514,75.184 49.276,75.184 50.038,75.184 50.8,75.184 47.371,75.946 48.133,75.946 48.895,75.946 49.657,75.946 50.419,75.946 46.99,76.708 46.99,78.232 47.752,78.232 50.038,78.232 50.8,78.232 46.99,91.948 47.752,91.948 48.514,91.948 49.276,91.948 50.038,91.948 50.8,91.948 50.8,93.472 47.371,94.234 48.133,94.234 48.895,94.234 49.657,94.234 50.419,94.234 46.99,94.996 47.752,94.996 48.514,94.996 49.276,94.996 50.038,94.996 50.8,94.996 47.371,95.758 48.133,95.758 48.895,95.758 49.657,95.758 50.419,95.758 46.99,96.52 47.752,96.52 48.514,96.52 49.276,96.52 50.038,96.52 50.8,96.52 47.371,97.282 48.133,97.282 48.895,97.282 49.657,97.282 50.419,97.282 46.99,98.044 47.752,98.044 48.514,98.044 49.276,98.044 50.038,98.044 50.8,98.044
DTEN_1: IC1400_1.52 R1406_1.2 R1407_1.1 | length 11.1
  Top w0.152: v1(131.38,58.737) 131.38,58.837 131.98,59.437 R1406_1.2@132.08,59.437 ; R1406_1.2@132.08,59.488 R1407_1.1@132.08,60.527 ; v1(137.719,56.972) 138.1,56.972 138.457,56.615 IC1400_1.52@138.457,55.598
  Bottom w0.152: v1(131.38,58.737) 135.953,58.737 v1(137.719,56.972)
DTEN_2: IC1400_2.52 R1406_2.2 R1407_2.1 | length 13.5
  Top w0.152: v1(77.47,58.788) 77.47,59.69 77.787,60.008 78.422,60.008 ; R1407_2.1@78.307,60.527 R1407_2.1@78.422,60.527 ; R1406_2.2@78.422,59.488 78.422,60.008 ; R1407_2.1@78.422,60.736 R1407_2.1@78.422,60.527 ; v1(84.583,57.119) 84.799,56.902 84.799,56.854 85.117,56.536 IC1400_2.52@85.117,55.598 ; 78.422,60.008 R1407_2.1@78.422,60.527
  Bottom w0.152: v1(77.47,58.788) 83.77,58.788 84.138,58.42 84.138,57.468 84.486,57.119 v1(84.583,57.119)
EXT_DC_IN+: F900.1 X1000.1 X1000.3 X1001.1 X1002.1 | length 25.2
  Top w0.813: F900.1@6.33,15.873 9.523,15.873 X1000.1@9.842,16.192
  SUPPLY w0.813: X1000.3@12.383,16.192 X1000.1@9.842,16.192 9.842,7.771 10.795,6.818 X1002.1@12.5,6.818 X1001.1@20,6.818
EXT_DC_IN-: C900.1 C902.1 C903.1 C904.1 C906.1 IC900.4 IC900.9 R901.1 R905.1 TP900.1 X1000.2 X1000.4 X1001.2 X1002.2 | length 105.8
  Top w0.152: X1000.4@12.383,18.732 TP900.1@12.383,22.225
  Top w0.406: v1(9.525,85.407) C904.1@10.405,85.407 C904.1@10.705,85.407 ; v1(9.525,88.582) R901.1@10.73,88.582
  Top w0.813: v2(11.43,74.612) 11.82,74.612 12.296,75.089 C900.1@12.296,76.041
  Signals1 w0.813: v2(11.43,74.612) 1.27,74.612 0.61,73.952 0.61,21.298 1.429,20.479 11.747,20.479 12.383,19.844 X1000.4@12.383,18.732
  SUPPLY w0.813: X1000.2@9.842,18.732 X1000.4@12.383,18.732 13.652,18.732 14.287,18.098 14.287,9.815 ; X1002.2@12.383,9.932 X1002.2@12.5,9.815 14.287,9.815 ; X1001.2@20,9.815 14.287,9.815
  other v1: 13.462,75.946 14.224,75.946 14.986,75.946 15.748,75.946 16.51,75.946 17.272,75.946 18.034,75.946 18.796,75.946 19.558,75.946 20.32,75.946 21.082,75.946 21.844,75.946 22.606,75.946 23.368,75.946 24.13,75.946 24.892,75.946 25.654,75.946 13.843,76.708 14.605,76.708 15.367,76.708 16.129,76.708 16.891,76.708 17.653,76.708 18.415,76.708 19.177,76.708 19.939,76.708 20.701,76.708 21.463,76.708 22.225,76.708 22.987,76.708 23.749,76.708 24.511,76.708 25.273,76.708 26.035,76.708 13.462,77.47 14.224,77.47 14.986,77.47 15.748,77.47 16.51,77.47 17.272,77.47 18.034,77.47 18.796,77.47 19.558,77.47 20.32,77.47 21.082,77.47 21.844,77.47 22.606,77.47 23.368,77.47 24.13,77.47 24.892,77.47 25.654,77.47 13.843,78.232 14.605,78.232 15.367,78.232 16.129,78.232 16.891,78.232 17.653,78.232 18.415,78.232 19.177,78.232 19.939,78.232 20.701,78.232 21.463,78.232 22.225,78.232 22.987,78.232 23.749,78.232 24.511,78.232 25.273,78.232 26.035,78.232 13.462,78.994 14.224,78.994 14.986,78.994 15.748,78.994 16.51,78.994 17.272,78.994 18.034,78.994 18.796,78.994 19.558,78.994 20.32,78.994 21.082,78.994 21.844,78.994 22.606,78.994 23.368,78.994 24.13,78.994 24.892,78.994 25.654,78.994 7.747,79.756 8.509,79.756 9.271,79.756 10.033,79.756 10.795,79.756 11.557,79.756 12.319,79.756 13.081,79.756 13.843,79.756 14.605,79.756 15.367,79.756 16.129,79.756 16.891,79.756 8.128,80.518 8.89,80.518 9.652,80.518 10.414,80.518 11.176,80.518 11.938,80.518 12.7,80.518 13.462,80.518 14.224,80.518 14.986,80.518 15.748,80.518 16.51,80.518 13.843,81.28 14.605,81.28 15.367,81.28 16.129,81.28 16.891,81.28 13.462,82.042 14.224,82.042 14.986,82.042 15.748,82.042 16.51,82.042 14.605,82.804 15.367,82.804 16.129,82.804 16.891,82.804 15.642,83.672 16.742,83.672 15.642,84.772 16.742,84.772 15.642,85.873 16.742,85.873 15.367,87.376 16.129,87.376 16.891,87.376 16.51,88.138 16.129,88.9
EXT_DC_ISO+: C608_1.1 C608_2.1 C907.2 C908.2 D901.1 D1400_1.2 D1400_2.2 D1401_1.1 D1401_2.1 Q600_1.4 Q600_2.4 R607_1.2 R607_2.2 R609_1.2 R609_2.2 R1401_1.1 R1401_2.1 TP902.1 X900.1 | length 169.6
  Top w0.152: v1(44.704,74.422) 44.926,74.2 TP902.1@44.926,72.866 ; v1(44.704,75.946) v1@44.767,75.882
  Top w0.254: D1401_2.1@70.802,61.115 72.125,61.115 72.625,60.615 R1401_2.1@73.66,60.615
  Top w0.406: v3(45.72,44.133) 46.102,44.515 R607_2.2@46.988,44.515 ; D1400_2.2@51.752,37.68 v3(51.752,41.275) ; v3(69.215,62.547) v3(69.215,61.277) 69.377,61.115 D1401_2.1@70.802,61.115 ; v3(100.33,45.257) 100.33,44.862 100.36,44.832 ; R607_1.2@101.6,44.832 100.36,44.832 ; D1400_1.2@105.093,37.68 105.093,38.13 103.638,39.585 102.337,39.585 100.762,41.16 100.762,44.43 100.36,44.832 ; v3(123.19,63.182) 124.429,63.182 125.095,62.517 D1401_1.1@125.095,61.215 ; D1401_1.1@125.095,61.115 126.383,61.115 126.883,60.615 R1401_1.1@127.635,60.615
  Signals2 w0.406: v3(45.72,44.133) 46.038,43.815 51.752,43.815 ; v3(51.752,41.275) 51.752,43.815 ; v3(69.215,61.277) v3(46.99,61.277) 46.626,60.914 46.626,53.386 51.752,48.26 51.752,43.815 ; v3(69.215,62.547) 69.896,63.229 77.89,63.229 78.254,62.865 100.33,62.865 ; v3(100.33,45.257) 100.33,46.979 100.284,47.025 100.284,47.59 100.33,47.636 100.33,62.865 ; v3(123.19,63.182) 122.555,63.182 122.237,62.865 100.33,62.865
  Bottom w0.406: X900.1@41.593,75.248 41.656,75.184 41.656,66.611 v3(46.99,61.277)
  other v1: 43.18,74.422 43.942,74.422 43.561,75.184 44.323,75.184 45.085,75.184 43.18,75.946 43.942,75.946 41.275,76.708 42.037,76.708 42.799,76.708 43.561,76.708 44.323,76.708 45.085,76.708 41.656,77.47 42.418,77.47 41.275,78.232 42.037,78.232 42.799,78.232 41.656,78.994 42.418,78.994 41.275,79.756 42.037,79.756 42.799,79.756 41.656,80.518 42.418,80.518 41.275,81.28 42.037,81.28 42.799,81.28 41.656,82.042 42.418,82.042 41.275,82.804 42.037,82.804 42.799,82.804 41.656,83.566 42.418,83.566 41.275,84.328 42.037,84.328 42.799,84.328 41.656,85.09 42.418,85.09 41.275,85.852 42.037,85.852 42.799,85.852 41.656,86.614 42.418,86.614 41.275,87.376 42.037,87.376 42.799,87.376 41.656,88.138 42.418,88.138 41.275,88.9 42.037,88.9 42.799,88.9
FB_1: C604_1.1 R602_1.2 R603_1.1 U600_1.9 | length 14.4
  Top w0.406: v1(114.935,48.578) 114.617,48.578 114.3,48.895 114.3,49.892 114.543,50.135 U600_1.9@115.345,50.135 ; v1(120.015,46.99) 120.809,47.784 120.809,48.578 ; R603_1.1@120.08,48.578 120.809,48.578 ; C604_1.1@121.513,46.99 121.513,48.001 121.538,48.026 R602_1.2@121.538,48.578 120.809,48.578
  Signals1 w0.406: v1(114.935,48.578) 114.935,47.307 115.252,46.99 v1(120.015,46.99)
FB_2: C604_2.1 R602_2.2 R603_2.1 U600_2.9 | length 14.4
  Top w0.406: v1(60.325,48.578) 60.008,48.578 59.69,48.895 59.69,49.892 59.933,50.135 U600_2.9@60.735,50.135 ; v1(65.405,46.99) 66.199,47.784 66.199,48.578 ; R603_2.1@65.47,48.578 66.199,48.578 ; C604_2.1@66.903,46.99 66.903,48.001 66.928,48.026 R602_2.2@66.928,48.578 66.199,48.578
  Signals1 w0.406: v1(60.325,48.578) 60.325,47.307 60.642,46.99 v1(65.405,46.99)
FUSED_CELL.CELL_0+: F318.2 R1305_1.1 R1305_2.1 R1504.1 R1510.1 T1505.2 U1104.2 | length 215.4
  Top w0.152: U1104.2@116.522,63.817 116.522,62.841 116.816,62.547 118.427,62.547 118.745,62.865 118.745,64.77 119.079,65.104 131.281,65.104 131.595,65.418 143.72,65.418 146.248,67.945 147.226,67.945 147.635,68.354 T1505.2@147.635,70.17
  Top w0.254: R1305_2.1@95.865,29.133 95.865,28.436 v1(95.885,28.416) ; v2(147.955,22.701) 147.955,27.983 149.105,29.133 R1305_1.1@149.205,29.133
  Top w0.406: R1510.1@140.315,88.53 140.315,91.102 v1(140.335,91.123) ; R1504.1@140.335,81.65 142.187,81.65 v1(142.24,81.597) ; T1505.2@147.635,70.17 147.635,71.435 v1(147.637,71.438) ; F318.2@147.955,21.593 v2(147.955,22.701)
  Signals2 w0.406: v1(140.335,91.123) 140.653,90.805 150.495,90.805 158.115,83.185 158.115,81.597 158.115,70.619 158.115,24.13 158.115,23.747 157.275,22.906 148.16,22.906 v2(147.955,22.701)
  SUPPLY w0.406: v1(142.24,81.597) 142.24,79.692 143.192,78.74 143.192,71.755 143.51,71.438 v1(147.637,71.438)
  Bottom w0.152: v1(95.885,28.416) 96.374,27.928 147.637,27.928 147.955,27.61 v2(147.955,22.701)
  other v1: 138.43,82.042 138.811,82.804 139.573,82.804 140.335,82.804 141.097,82.804 141.859,82.804 138.43,83.566 139.192,83.566 139.954,83.566 140.716,83.566 141.478,83.566 142.24,83.566 138.811,84.328 139.573,84.328 140.335,84.328 141.097,84.328 141.859,84.328 138.43,85.09 139.192,85.09 139.954,85.09 140.716,85.09 141.478,85.09 142.24,85.09 138.811,85.852 139.573,85.852 140.335,85.852 141.097,85.852 141.859,85.852 138.43,86.614 139.192,86.614 139.954,86.614 140.716,86.614 141.478,86.614 142.24,86.614 138.811,87.376 139.573,87.376 140.335,87.376 141.097,87.376 141.859,87.376
FUSED_CELL.CELL_0-: F319.2 R1306_1.1 R1306_2.1 R1505.1 R1511.1 U1105.2 | length 212.3
  Top w0.152: U1105.2@119.697,63.817 119.697,62.841 119.991,62.547 121.285,62.547 121.602,62.865 121.602,63.458 122.66,64.516 131.55,64.516 131.797,64.763 148.59,64.763 148.907,65.08 148.907,81.28 148.537,81.65 R1505.1@146.05,81.65
  Top w0.254: R1306_2.1@98.405,29.133 98.505,29.133 98.876,28.762 99.191,28.762 v1(99.377,28.575) ; v2(149.86,21.907) 149.86,27.348 151.645,29.133 R1306_1.1@151.745,29.133
  Top w0.406: R1511.1@146.05,88.582 v1(146.05,91.757) ; F319.2@149.86,16.258 F319.2@149.86,16.513 v2(149.86,21.907)
  Signals2 w0.406: v1(146.05,91.757) 146.368,91.44 150.812,91.44 158.75,83.503 158.75,70.619 158.75,22.543 157.751,21.544 150.224,21.544 v2(149.86,21.907)
  Bottom w0.152: v1(99.377,28.575) 99.707,28.245 149.542,28.245 149.86,27.928 v2(149.86,21.907)
  other v1: 144.907,82.804 145.669,82.804 146.431,82.804 147.193,82.804 147.955,82.804 144.526,83.566 145.288,83.566 146.05,83.566 146.812,83.566 147.574,83.566 144.907,84.328 145.669,84.328 146.431,84.328 147.193,84.328 147.955,84.328 144.526,85.09 145.288,85.09 146.05,85.09 146.812,85.09 147.574,85.09 144.907,85.852 145.669,85.852 146.431,85.852 147.193,85.852 147.955,85.852 144.526,86.614 145.288,86.614 146.05,86.614 146.812,86.614 147.574,86.614 144.907,87.376 145.669,87.376 146.431,87.376 147.193,87.376 147.955,87.376
FUSED_CELL.CELL_1+: F317.2 R1304_1.1 R1304_2.1 R1503.1 R1509.1 T1504.2 U1103.2 | length 223.7
  Top w0.152: U1103.2@113.347,63.817 113.347,62.841 113.641,62.547 115.252,62.547 115.57,62.865 115.57,65.095 116.197,65.722 130.925,65.722 131.243,66.04 138.365,66.04 140.27,67.945 141.67,67.945 141.92,68.195 T1504.2@141.92,70.17
  Top w0.254: R1304_2.1@93.325,29.133 93.325,28.436 v1(93.345,28.416) ; v2(146.05,22.543) 146.05,28.618 146.565,29.133 R1304_1.1@146.665,29.133
  Top w0.406: R1503.1@134.62,81.65 136.472,81.65 v1(136.525,81.597) ; R1509.1@134.62,88.53 v1(134.62,90.487) ; T1504.2@141.92,70.17 141.92,71.435 v1(141.922,71.438) ; F317.2@146.05,16.513 v2(146.05,22.543)
  Signals2 w0.406: v1(134.62,90.487) 134.937,90.17 150.177,90.17 157.48,82.867 157.48,81.597 157.48,70.619 157.48,24.13 156.845,23.495 147.002,23.495 v2(146.05,22.543)
  SUPPLY w0.406: v1(136.525,81.597) 136.525,79.692 137.477,78.74 137.477,71.755 137.795,71.438 v1(141.922,71.438)
  Bottom w0.152: v1(93.345,28.416) 93.885,27.877 95.631,27.877 95.897,27.61 145.732,27.61 146.05,27.293 v2(146.05,22.543)
  other v1: 133.477,82.804 134.239,82.804 135.001,82.804 135.763,82.804 136.525,82.804 133.096,83.566 133.858,83.566 134.62,83.566 135.382,83.566 136.144,83.566 133.477,84.328 134.239,84.328 135.001,84.328 135.763,84.328 136.525,84.328 133.096,85.09 133.858,85.09 134.62,85.09 135.382,85.09 136.144,85.09 133.477,85.852 134.239,85.852 135.001,85.852 135.763,85.852 136.525,85.852 133.096,86.614 133.858,86.614 134.62,86.614 135.382,86.614 136.144,86.614 133.477,87.376 134.239,87.376 135.001,87.376 135.763,87.376 136.525,87.376
FUSED_CELL.CELL_2+: F316.2 R1303_1.1 R1303_2.1 R1502.1 R1508.1 T1503.2 U1102.2 | length 220.9
  Top w0.152: U1102.2@110.172,63.817 110.172,62.841 110.466,62.547 112.078,62.547 112.395,62.865 112.395,65.087 113.665,66.358 130.56,66.358 130.878,66.675 133.285,66.675 134.555,67.945 135.955,67.945 136.217,68.207 T1503.2@136.217,70.17
  Top w0.254: v1(90.785,28.416) R1303_2.1@90.785,29.133 ; R1303_1.1@144.125,29.133 144.125,22.563 v2(144.145,22.543)
  Top w0.406: R1502.1@128.905,81.65 130.757,81.65 v1(130.81,81.597) ; R1508.1@128.905,88.53 v1(128.905,89.535) ; T1503.2@136.217,70.17 v1(136.217,71.428) ; F316.2@144.145,21.338 F316.2@144.145,21.593 v2(144.145,22.543)
  Signals2 w0.406: v1(128.905,89.535) 149.86,89.535 156.845,82.55 156.845,81.597 156.845,70.619 156.845,24.765 156.21,24.13 145.732,24.13 v2(144.145,22.543)
  SUPPLY w0.406: v1(130.81,81.597) 130.81,79.692 131.762,78.74 131.762,71.755 132.09,71.428 v1(136.217,71.428)
  Bottom w0.152: v1@90.805,28.416 92.551,28.416 93.345,27.622 95.25,27.622 95.58,27.293 143.827,27.293 144.145,26.975 v2(144.145,22.543)
  other v1: 127,82.042 127.381,82.804 128.143,82.804 128.905,82.804 129.667,82.804 130.429,82.804 127,83.566 127.762,83.566 128.524,83.566 129.286,83.566 130.048,83.566 130.81,83.566 127.381,84.328 128.143,84.328 128.905,84.328 129.667,84.328 130.429,84.328 127,85.09 127.762,85.09 128.524,85.09 129.286,85.09 130.048,85.09 130.81,85.09 127.381,85.852 128.143,85.852 128.905,85.852 129.667,85.852 130.429,85.852 127,86.614 127.762,86.614 128.524,86.614 129.286,86.614 130.048,86.614 130.81,86.614 127.381,87.376 128.143,87.376 128.905,87.376 129.667,87.376 130.429,87.376 127,89.662 127.762,89.662 130.048,89.662 130.81,89.662
FUSED_CELL.CELL_3+: F315.2 R1302_1.1 R1302_2.1 R1501.1 R1507.1 T1502.2 U1101.2 | length 229.2
  Top w0.152: U1101.2@106.998,63.817 106.998,62.841 107.291,62.547 108.902,62.547 109.22,62.865 109.22,64.477 110.148,65.405 111.093,65.405 112.68,66.992 127.887,66.992 128.84,67.945 129.854,67.945 130.49,68.581 T1502.2@130.49,70.17
  Top w0.254: R1302_2.1@88.245,29.133 88.245,28.436 v1(88.265,28.416) ; R1302_1.1@141.585,29.133 141.685,29.133 142.24,28.577 v2(142.24,22.543)
  Top w0.406: R1501.1@123.19,81.65 125.042,81.65 v1(125.095,81.597) ; R1507.1@123.19,88.53 v1(123.19,89.535) ; T1502.2@130.49,70.17 130.49,71.435 v1(130.493,71.438) ; F315.2@142.24,16.513 v2(142.24,22.543)
  Signals2 w0.406: v1(123.19,89.535) 123.871,88.854 149.589,88.854 156.21,82.233 156.21,81.597 156.21,70.619 156.21,25.4 155.575,24.765 144.463,24.765 v2(142.24,22.543)
  SUPPLY w0.406: v1(125.095,81.597) 125.095,79.692 126.047,78.74 126.047,71.755 126.365,71.438 v1(130.493,71.438)
  Bottom w0.152: v1(88.265,28.416) 90.011,28.416 90.231,28.197 90.231,28.187 90.795,27.622 92.71,27.622 93.027,27.305 94.932,27.305 95.262,26.975 141.922,26.975 142.24,26.658 v2(142.24,22.543)
  other v1: 122.047,82.804 122.809,82.804 123.571,82.804 124.333,82.804 125.095,82.804 121.666,83.566 122.428,83.566 123.19,83.566 123.952,83.566 124.714,83.566 122.047,84.328 122.809,84.328 123.571,84.328 124.333,84.328 125.095,84.328 121.666,85.09 122.428,85.09 123.19,85.09 123.952,85.09 124.714,85.09 122.047,85.852 122.809,85.852 123.571,85.852 124.333,85.852 125.095,85.852 121.666,86.614 122.428,86.614 123.19,86.614 123.952,86.614 124.714,86.614 122.047,87.376 122.809,87.376 123.571,87.376 124.333,87.376 125.095,87.376 121.666,89.662 122.428,89.662 123.952,89.662 124.714,89.662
